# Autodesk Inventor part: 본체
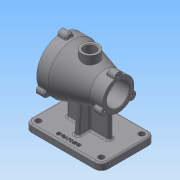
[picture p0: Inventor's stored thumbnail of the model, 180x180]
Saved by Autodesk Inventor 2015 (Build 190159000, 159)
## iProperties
Created: 2020-03
Part Number: 본체
Material: 일반
Document SubType Name: Modeling
Designer: user
Density: 1 g/cm^3
Appearance: 기본값
Author: user
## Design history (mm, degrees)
sketch "스케치1"
  geometry: 1 further point
node "작업 평면1"
sketch "스케치2"
  geometry: L1 (-67.5, -47.5)-(67.5, -47.5); L2 (67.5, -47.5)-(67.5, 47.5); L3 (67.5, 47.5)-(-67.5, 47.5); L4 (-67.5, 47.5)-(-67.5, -47.5); L5 (-67.5, -47.5)-(67.5, 47.5); L6 (67.5, -47.5)-(-67.5, 47.5); 1 further point
  constraints: 12 end point, 2 midpoint, 2 parallel, 1 horizontal, 1 perpendicular
  dimensions: "d1" = 135 distance of L3.end L2.end; "d2" = 95 distance of L2.end L1.end
extrude "돌출1" new body sketch "스케치2" distance "d3" = 12; taper "d4" = 0 deg
sketch "스케치3"
  geometry: L1 (-50, 0)-(50, 0); L2 (-50, 0)-(-50, 44); L3 (-50, 44)-(-30, 44); L4 (50, 0)-(50, 27.5); L5 (50, 27.5)-(27, 27.5); L6 (27, 27.5)-(-30, 44); 2 further points
  constraints: 12 end point, 2 perpendicular, 2 vertical, 1 coincident, 1 horizontal, 1 midpoint
  dimensions: "d5" = 100 distance of L1.start L1.end; "d6" = 44 distance of L1.start L2.end; "d7" = 20 distance of L2.end L3.end; "d8" = 27.5 distance of L1.end L4.end; "d9" = 23 distance of L4.end L5.end
revolve "회전1" sketch "스케치3" stored, may be unused: angle "d10" = 90 deg
sketch "스케치4"
  geometry: L1 (0, 0)-(37, 0); L2 (37, 0)-(37, -82); L3 (37, -82)-(0, -82); L4 (0, 0)-(-37, 0); L5 (-37, 0)-(-37, -82); L6 (-37, -82)-(0, -82)
  constraints: 12 end point, 3 horizontal, 3 perpendicular
  dimensions: "d11" = 37 distance of L3.end L2.end; "d12" = 37 distance of L1.start L4.end
extrude "돌출2" join sketch "스케치4" stored distance "d13" = 8; taper "d14" = 0 deg
sketch "스케치8"
  geometry: L1 (0, 0)-(0, -75); L2 (0, -75)-(-25, -75); L3 (-25, -75)-(-20.363, -22); L4 (-20.363, -22)-(0, -22); L5 (0, -75)-(25, -75); L6 (0, -75)-(25, -75); L7 (25, -75)-(20.363, -22); L8 (20.363, -22)-(0, -22)
  constraints: 16 end point, 3 perpendicular, 2 horizontal, 1 collinear, 1 point on line, 1 vertical
  dimensions: "d24" = 75 distance of L1.start L1.end; "d25" = 25 distance of L1.end L2.end; "d26" = 85 deg angle of L2 L3; "d27" = 25 distance of L1.end L5.end; "d28" = 0 distance between parallel lines of L5 L6 (derived); "d29" = 85 deg angle of L7 L5
extrude "돌출6" join sketch "스케치8" stored distance "d30" = 8; taper "d31" = 0 deg
sketch "스케치5"
  geometry: C1 r 44 at (0, 0) reference; C2 r 36 at (0, 0)
  constraints: 1 centre point, 1 coincident
  dimensions: "d15" = 72 diameter of C2
extrude "돌출3" cut sketch "스케치5" distance "d16" = 23; taper "d17" = 0 deg
sketch "스케치6"
  geometry: C1 r 36 at (0, 0) reference; C2 r 26 at (0, 0)
  constraints: 1 centre point, 1 coincident
  dimensions: "d18" = 52 diameter of C2
extrude "돌출4" cut sketch "스케치6" distance "d19" = 47; taper "d20" = 0 deg
sketch "스케치7"
  geometry: C1 r 26 at (0, 0) reference; C2 r 20 at (0, 0)
  constraints: 1 centre point, 1 coincident
  dimensions: "d21" = 40 diameter of C2
extrude "돌출5" cut sketch "스케치7" stored distance "d22" = 47; taper "d23" = 0 deg
sketch "스케치9"
  geometry: C1 r 7 at (44, 0); 1 further point
  constraints: 1 centre point, 1 horizontal alignment, 1 other
  dimensions: "d32" = 14 diameter of C1
extrude "돌출7" join sketch "스케치9" distance "d33" = 15; taper "d34" = 0 deg
sketch "스케치10"
  geometry: A1 r 7 centre (0, 0) between (-0.557, -6.978) and (-0.557, 6.978) reference; 1 further point
  constraints: 1 coincident
hole "구멍1" sketch "스케치10" at (0, 0) diameter "d35" = 4.134; stored, may be unused: countersink angle "d39" = 90 deg, drill point angle "d41" = 118 deg; dims "d36" = 9, "d37" = 4, "d38" = 2, "d40" = 11
sketch "스케치11"
  geometry: C1 r 7 at (-27.5, 0); 1 further point
  constraints: 1 centre point, 1 horizontal alignment, 1 other
  dimensions: "d45" = 14 diameter of C1
extrude "돌출8" join sketch "스케치11" distance "d46" = 15; taper "d47" = 0 deg
sketch "스케치12"
  geometry: A1 r 7 centre (0, 0) between (0.891, 6.943) and (0.891, -6.943) reference; 1 further point
  constraints: 1 coincident
hole "구멍2" sketch "스케치12" at (0, 0) diameter "d48" = 4.134; stored, may be unused: countersink angle "d52" = 90 deg, drill point angle "d54" = 118 deg; dims "d49" = 9, "d50" = 4, "d51" = 2, "d53" = 11
node "작업 평면2"
sketch "스케치13"
  geometry: C1 r 15 at (0, 0); 1 further point
  constraints: 1 centre point, 1 coincident
  dimensions: "d56" = 30 diameter of C1
extrude "돌출9" join sketch "스케치13" distance "d57" = 15; taper "d58" = 0 deg
sketch "스케치14"
  geometry: C1 r 15 at (0, 0) reference; C2 r 10 at (0, 0)
  constraints: 1 centre point, 1 coincident
  dimensions: "d59" = 20 diameter of C2
extrude "돌출10" cut sketch "스케치14" distance "d60" = 30; taper "d61" = 0 deg
fillet "모깎기1" dims "d62" = 12
sketch "스케치15"
  geometry: C1 r 5 at (-55.5, -35.5); C2 r 5 at (-55.5, 35.5); C3 r 5 at (55.5, 35.5); C4 r 5 at (55.5, -35.5); A1 r 12 centre (-55.5, 35.5) between (-55.5, 47.5) and (-67.5, 35.5) reference; A2 r 12 centre (-55.5, -35.5) between (-67.5, -35.5) and (-55.5, -47.5) reference; A3 r 12 centre (55.5, -35.5) between (55.5, -47.5) and (67.5, -35.5) reference; A4 r 12 centre (55.5, 35.5) between (67.5, 35.5) and (55.5, 47.5) reference; 1 further point
  constraints: 4 centre point, 4 coincident
  dimensions: "d63" = 10 diameter of C1; "d64" = 10 diameter of C2; "d65" = 10 diameter of C3; "d66" = 10 diameter of C4
extrude "돌출11" cut sketch "스케치15" distance "d67" = 30; taper "d68" = 0 deg
fillet "모깎기2" dims "d69" = 3
fillet "모깎기3" dims "d73" = 1
fillet "모깎기4" dims "d79" = 3
fillet "모깎기5" dims "d80" = 3
chamfer "모따기1" distance "d81" = 1; stored, may be unused: second distance "d82" = 2, angle "d83" = 45 deg
fillet "모깎기6" dims "d84" = 3
fillet "모깎기7" dims "d85" = 3
node "작업 평면4"
sketch "스케치17"
  geometry: L1 (-55.5, -47.5)-(55.5, -47.5) reference; 2 further points
  constraints: 1 vertical alignment, 1 other
  dimensions: "d87" = 10 distance from line of L1 point (0, -37.5)
feature "엠보싱1" sketch "스케치17" dims "d11" = 37, "d12" = 37, "d88" = 1, "d89" = 0
node "솔리드1"
pattern_circular "원형 패턴3" dims "d75" = 360 deg
other parameters: "d0" = -87, "d55" = 45, "d86" = 27.5
